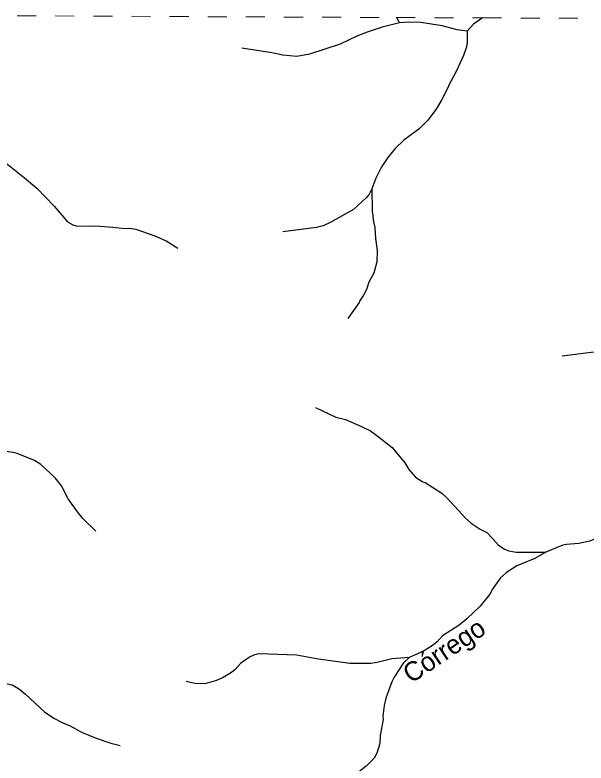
# Model space of a CAD drawing. Extents: x 551.6 to 577.6, y 7567 to 7594.7.
# Drawn here: x 568.585 to 571.58, y 7590.742 to 7594.669 of the extents above; entities that cross this region are included whole.
import ezdxf
from ezdxf.enums import TextEntityAlignment as Align

# ---------------------------------------------------------------- set-up
doc = ezdxf.new("R2010")
doc.units = 0
doc.header["$LTSCALE"] = 0.04
doc.linetypes.add('SHORT_DASHED', pattern=[2.7, 1.5, -1.2])
doc.layers.add('53', color=7, linetype='SHORT_DASHED', lineweight=13)
doc.layers.add('7', color=7, linetype='Continuous', lineweight=25)
doc.layers.add('61', color=7, linetype='Continuous')

msp = doc.modelspace()

# ---------------------------------------------------------------- linework, layer by layer
at = {"layer": '53'}
msp.add_lwpolyline([(567.5959, 7594.6695), (570.5848, 7594.6561), (571.0376, 7594.6541), (573.1172, 7594.6449), (573.2827, 7594.6441)], dxfattribs=at)
at = {"layer": '7'}
for points in [[(570.6021, 7594.6279), (570.5117, 7594.6053), (570.4329, 7594.5795), (570.3781, 7594.5578), (570.2912, 7594.5167), (570.1303, 7594.4628), (570.0627, 7594.4507), (569.9902, 7594.4588), (569.9323, 7594.47), (569.7754, 7594.495)], [(570.5848, 7594.6561), (570.5922, 7594.6487), (570.5938, 7594.6399), (570.597, 7594.6391), (570.6021, 7594.6279)], [(570.9564, 7594.5848), (570.9045, 7594.5916), (570.8256, 7594.6117), (570.7146, 7594.6294), (570.6518, 7594.631), (570.6021, 7594.6279)], [(571.0376, 7594.6541), (570.9898, 7594.6205), (570.9564, 7594.5848)], [(570.9564, 7594.5848), (570.956, 7594.5248), (570.9528, 7594.5023), (570.9375, 7594.4572), (570.8996, 7594.3719), (570.8602, 7594.3011), (570.857, 7594.2898), (570.8216, 7594.2222), (570.7934, 7594.1755), (570.7499, 7594.1176), (570.7033, 7594.0693), (570.6252, 7594.0121), (570.5785, 7593.9687), (570.5399, 7593.922), (570.5061, 7593.8681), (570.4779, 7593.8133), (570.456, 7593.7572), (570.4586, 7593.6411)], [(567.9199, 7594.4085), (567.9815, 7594.3703), (568.0201, 7594.3405), (568.1102, 7594.2592), (568.1915, 7594.1932), (568.2494, 7594.1329), (568.2961, 7594.0733), (568.3549, 7594.0161), (568.5392, 7593.8922), (568.6349, 7593.8141)], [(568.6349, 7593.8141), (568.6993, 7593.7602), (568.7895, 7593.6652), (568.8595, 7593.5832), (568.8877, 7593.5671), (568.9102, 7593.5606), (569.0068, 7593.5622), (569.0985, 7593.5558), (569.1629, 7593.5477), (569.1854, 7593.5494), (569.2192, 7593.5445), (569.319, 7593.5107), (569.377, 7593.4834), (569.4389, 7593.4448)], [(570.456, 7593.7572), (570.4401, 7593.7256), (570.4296, 7593.7119), (570.3612, 7593.6483), (570.2389, 7593.5799), (570.2011, 7593.5622), (570.1657, 7593.5534), (569.9894, 7593.5301)], [(570.4586, 7593.6411), (570.4651, 7593.5832), (570.4723, 7593.5542), (570.4763, 7593.4963), (570.4852, 7593.4335), (570.4836, 7593.3739), (570.4667, 7593.3144), (570.4409, 7593.2661), (570.428, 7593.2275), (570.4135, 7593.1985), (570.3918, 7593.1671), (570.391, 7593.1606), (570.3307, 7593.0753)], [(571.4558, 7592.8798), (571.6079, 7592.8991), (571.7334, 7592.9055), (571.8075, 7592.9039), (571.8638, 7592.8975), (571.9475, 7592.8798), (572.0618, 7592.8452), (572.1495, 7592.7993), (572.2549, 7592.7244), (572.3443, 7592.6343), (572.4513, 7592.5071), (572.4803, 7592.4822), (572.506, 7592.4653), (572.5189, 7592.4597), (572.5503, 7592.4556)], [(570.1617, 7592.6078), (570.2671, 7592.5578), (570.3186, 7592.545), (570.4023, 7592.5096), (570.449, 7592.4854), (570.4828, 7592.4613), (570.5632, 7592.3977), (570.6296, 7592.3176), (570.6502, 7592.2834), (570.6864, 7592.2432), (570.7234, 7592.2182), (570.7371, 7592.215), (570.8232, 7592.1595), (570.8538, 7592.1313), (570.9479, 7592.0283), (570.9777, 7592.0009), (571.0244, 7591.9703), (571.0606, 7591.9518), (571.092, 7591.9189)], [(569.0084, 7591.9599), (568.94, 7592.0259), (568.9118, 7592.0605), (568.8635, 7592.1297), (568.8289, 7592.1973), (568.7959, 7592.24), (568.7195, 7592.3092), (568.6865, 7592.3301), (568.5963, 7592.3663), (568.5754, 7592.3727), (568.5352, 7592.3776), (568.4466, 7592.3792), (568.3468, 7592.3719), (568.2905, 7592.3631), (568.2374, 7592.3631), (568.1456, 7592.3743), (568.107, 7592.3824), (568.0684, 7592.3961), (568.0112, 7592.4275)], [(571.7109, 7591.9518), (571.5998, 7591.906), (571.5419, 7591.8939), (571.4775, 7591.8899), (571.4582, 7591.885), (571.3702, 7591.849)], [(571.092, 7591.9189), (571.1186, 7591.8882), (571.1524, 7591.8641), (571.1749, 7591.8552), (571.2135, 7591.8496), (571.3702, 7591.849)], [(571.3702, 7591.849), (571.3117, 7591.8166), (571.2176, 7591.7772), (571.1636, 7591.7426), (571.1306, 7591.7128), (571.0896, 7591.6549), (571.0759, 7591.6291), (571.0252, 7591.5647), (570.9552, 7591.4987), (570.9149, 7591.4665), (570.828, 7591.4094), (570.799, 7591.378), (570.7805, 7591.3627), (570.7371, 7591.3353), (570.6928, 7591.3136), (570.6518, 7591.2953)], [(570.6518, 7591.2953), (570.5616, 7591.2887), (570.4844, 7591.2702), (570.4506, 7591.2653), (570.3411, 7591.2637), (570.177, 7591.2879), (570.0611, 7591.3088), (569.8663, 7591.3144), (569.8405, 7591.3104), (569.8148, 7591.2983), (569.7681, 7591.2653), (569.7415, 7591.2348), (569.7214, 7591.2178), (569.6764, 7591.1905), (569.6426, 7591.1752), (569.5798, 7591.1575), (569.5283, 7591.1599), (569.4824, 7591.1704)], [(570.6518, 7591.2953), (570.622, 7591.2686), (570.5737, 7591.1929), (570.5616, 7591.1688), (570.531, 7591.0819), (570.5214, 7591.0432), (570.5149, 7590.9885), (570.5158, 7590.9708), (570.5005, 7590.8871), (570.498, 7590.8436), (570.4828, 7590.7945), (570.4683, 7590.7672), (570.4264, 7590.7253), (570.3862, 7590.6947), (570.2574, 7590.6247), (570.156, 7590.5837)], [(567.9974, 7591.1312), (568.1344, 7591.1253), (568.1988, 7591.1333), (568.3146, 7591.1559), (568.3871, 7591.1639), (568.4579, 7591.1655), (568.5448, 7591.1575), (568.5698, 7591.1519), (568.6036, 7591.1325), (568.6406, 7591.1028), (568.7404, 7591.0102), (568.7879, 7590.9772), (568.8329, 7590.9539)], [(568.8329, 7590.9539), (568.8739, 7590.9378), (568.9343, 7590.9048), (569.01, 7590.8726), (569.0873, 7590.8468), (569.1363, 7590.834)]]:
    msp.add_lwpolyline(points, dxfattribs=at)

# ---------------------------------------------------------------- texts
at = {"layer": '61'}
msp.add_text('Córrego', height=0.1, rotation=33.875, dxfattribs=at).set_placement((570.8634, 7591.2914), align=Align.CENTER)

doc.saveas('drawing.dxf')
